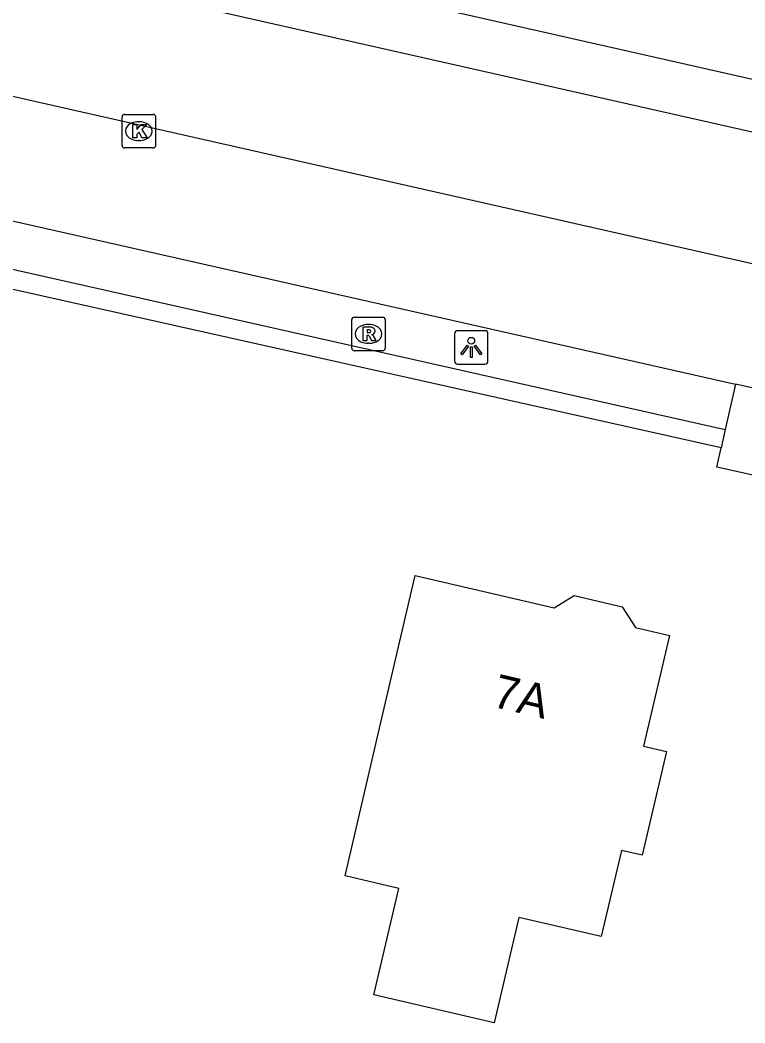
# Model space of a CAD drawing. Extents: x 161771 to 163125, y 382479 to 383177.
# Drawn here: x 162286.79 to 162308.4, y 383020.61 to 383050.51 of the extents above; entities that cross this region are included whole.
import ezdxf

# ---------------------------------------------------------------- set-up
doc = ezdxf.new("R2010")
doc.units = 0
for name, color, linetype in [('IMGEO_Berm_open', 7, 'Continuous'), ('IMGEO_Fietspad_gesloten', 7, 'Continuous'), ('IMGEO_Kolk', 7, 'Continuous'), ('IMGEO_Lichtpunt', 7, 'Continuous'), ('IMGEO_Pand', 7, 'Continuous'), ('IMGEO_Pand_nummerreeks', 7, 'Continuous'), ('IMGEO_Rijbaan_lokaal_gesloten', 7, 'Continuous'), ('IMGEO_Rioolput', 7, 'Continuous'), ('IMGEO_Voetpad_open', 7, 'Continuous')]:
    doc.layers.add(name, color=color, linetype=linetype)

msp = doc.modelspace()

# ---------------------------------------------------------------- linework, layer by layer
at = {"layer": 'IMGEO_Berm_open'}
for points in [[(162266.199, 383047.671), (162268.187, 383047.211), (162280.535, 383044.435), (162307.815, 383038.301)], [(162307.693, 383037.758), (162286.531, 383042.481), (162272.573, 383045.648)]]:
    msp.add_lwpolyline(points, dxfattribs=at)
at = {"layer": 'IMGEO_Fietspad_gesloten'}
msp.add_lwpolyline([(162315.791, 383045.55), (162268.595, 383056.213), (162263.052, 383057.484), (162259.124, 383058.343)], dxfattribs=at)
at = {"layer": 'IMGEO_Kolk'}
for p, q in [((162289.83, 383046.771), (162289.83, 383047.623)), ((162289.905, 383047.697), (162290.757, 383047.697)), ((162290.831, 383047.623), (162290.831, 383046.771)), ((162290.318, 383047.477), (162290.343, 383047.477)), ((162290.757, 383046.697), (162289.905, 383046.697)), ((162290.341, 383046.917), (162290.316, 383046.917))]:
    msp.add_line(p, q, dxfattribs=at)
for points in [[(162289.83, 383046.771), (162289.83, 383047.623)], [(162289.905, 383047.697), (162290.757, 383047.697)], [(162290.831, 383047.623), (162290.831, 383046.771)], [(162290.151, 383047.397), (162290.274, 383047.397), (162290.274, 383047.246), (162290.404, 383047.397), (162290.568, 383047.397), (162290.422, 383047.246), (162290.575, 383046.997), (162290.423, 383046.997), (162290.338, 383047.161), (162290.274, 383047.094), (162290.274, 383046.997), (162290.151, 383046.997), (162290.151, 383047.397)], [(162290.757, 383046.697), (162289.905, 383046.697)]]:
    msp.add_lwpolyline(points, dxfattribs=at)
for centre, start, end in [((162289.907, 383047.621), 91.552, 178.448), ((162289.907, 383047.621), 91.552, 178.448), ((162290.755, 383047.621), 1.552, 88.448), ((162290.755, 383047.621), 1.552, 88.448), ((162289.907, 383046.773), 181.552, 268.448), ((162289.907, 383046.773), 181.552, 268.448), ((162290.755, 383046.773), 271.552, 358.448), ((162290.755, 383046.773), 271.552, 358.448)]:
    msp.add_arc(centre, 0.0765, start, end, dxfattribs=at)
for centre, major_axis, ratio, start_param, end_param in [((162290.317, 383047.197), (-0.387, 0.002), 0.722429, 4.712389, 7.853982), ((162290.342, 383047.197), (-0.39, 0.002), 0.717154, 1.570796, 4.712389)]:
    msp.add_ellipse(centre, major_axis=major_axis, ratio=ratio, start_param=start_param, end_param=end_param, dxfattribs=at)
at = {"layer": 'IMGEO_Lichtpunt'}
for p, q in [((162299.743, 383041.151), (162299.743, 383040.344)), ((162299.743, 383041.151), (162299.743, 383040.344)), ((162300.645, 383041.246), (162299.837, 383041.246)), ((162300.645, 383041.246), (162299.837, 383041.246)), ((162300.739, 383040.344), (162300.739, 383041.151)), ((162300.739, 383040.344), (162300.739, 383041.151)), ((162299.837, 383040.25), (162300.645, 383040.25)), ((162299.837, 383040.25), (162300.645, 383040.25))]:
    msp.add_line(p, q, dxfattribs=at)
for points in [[(162300.117, 383040.815), (162300.156, 383040.787), (162299.968, 383040.525), (162299.93, 383040.552), (162300.117, 383040.815)], [(162300.219, 383040.767), (162300.266, 383040.767), (162300.266, 383040.445), (162300.219, 383040.445), (162300.219, 383040.767)], [(162300.329, 383040.787), (162300.367, 383040.814), (162300.554, 383040.552), (162300.515, 383040.524), (162300.329, 383040.787)]]:
    msp.add_lwpolyline(points, dxfattribs=at)
msp.add_circle((162300.242, 383040.949), 0.0994, dxfattribs=at)
for centre, start, end in [((162299.837, 383041.151), 90, 180), ((162299.837, 383041.151), 90, 180), ((162300.645, 383041.151), 0, 90), ((162300.645, 383041.151), 0, 90), ((162299.837, 383040.344), 180, 270), ((162299.837, 383040.344), 180, 270), ((162300.645, 383040.344), 270, 0), ((162300.645, 383040.344), 270, 360)]:
    msp.add_arc(centre, 0.0946, start, end, dxfattribs=at)
at = {"layer": 'IMGEO_Pand'}
msp.add_lwpolyline([(162304.719, 383025.754), (162304.118, 383023.183), (162301.664, 383023.756), (162300.929, 383020.608), (162297.34, 383021.447), (162298.081, 383024.617), (162296.48, 383024.991), (162297.578, 383029.691), (162298.573, 383033.948), (162302.711, 383032.981), (162303.309, 383033.352), (162304.743, 383033.017), (162305.135, 383032.399), (162306.148, 383032.163), (162305.376, 383028.86), (162306.065, 383028.7), (162305.342, 383025.608), (162304.719, 383025.754)], dxfattribs=at)
at = {"layer": 'IMGEO_Rijbaan_lokaal_gesloten'}
for points in [[(162270.405, 383051.883), (162283.923, 383048.832), (162329.67, 383038.487), (162387.404, 383025.398)], [(162269.608, 383048.319), (162269.978, 383048.272), (162271.762, 383047.863), (162308.119, 383039.657)], [(162312.021, 383038.776), (162311.795, 383038.827), (162311.766, 383038.834), (162308.119, 383039.657)]]:
    msp.add_lwpolyline(points, dxfattribs=at)
at = {"layer": 'IMGEO_Rioolput'}
for p, q in [((162296.676, 383040.724), (162296.676, 383041.576)), ((162296.751, 383041.65), (162297.603, 383041.65)), ((162297.677, 383041.576), (162297.677, 383040.724)), ((162297.164, 383041.43), (162297.189, 383041.43)), ((162297.187, 383040.87), (162297.162, 383040.87)), ((162297.603, 383040.65), (162296.751, 383040.65))]:
    msp.add_line(p, q, dxfattribs=at)
for points in [[(162296.676, 383040.724), (162296.676, 383041.576)], [(162296.751, 383041.65), (162297.603, 383041.65)], [(162297.677, 383041.576), (162297.677, 383040.724)], [(162297.265, 383041.348), (162297.013, 383041.35), (162297.013, 383040.95)], [(162297.013, 383040.95), (162297.137, 383040.95), (162297.137, 383041.112), (162297.148, 383041.112)], [(162297.191, 383041.269), (162297.137, 383041.269), (162297.137, 383041.188)], [(162297.137, 383041.188), (162297.189, 383041.188)], [(162297.195, 383041.083), (162297.266, 383040.95), (162297.406, 383040.95), (162297.341, 383041.076)], [(162297.603, 383040.65), (162296.751, 383040.65)]]:
    msp.add_lwpolyline(points, dxfattribs=at)
for centre, radius, start, end in [((162296.753, 383041.574), 0.0765, 91.552, 178.448), ((162296.753, 383041.574), 0.0765, 91.552, 178.448), ((162297.601, 383041.574), 0.0765, 1.552, 88.448), ((162297.601, 383041.574), 0.0765, 1.552, 88.448), ((162297.264, 383041.238), 0.109, 350.3612, 89.416), ((162297.147, 383041.059), 0.0533, 26.0293, 88.6989), ((162297.173, 383041.377), 0.19, 274.7715, 282.9687), ((162297.197, 383041.173), 0.0964, 77.0061, 93.1865), ((162297.211, 383041.23), 0.0378, 276.6634, 79.6772), ((162297.262, 383041.238), 0.112, 277.5842, 350.9817), ((162297.246, 383041.023), 0.108, 29.5134, 73.7905), ((162296.753, 383040.726), 0.0765, 181.552, 268.448), ((162296.753, 383040.726), 0.0765, 181.552, 268.448), ((162297.601, 383040.726), 0.0765, 271.552, 358.448), ((162297.601, 383040.726), 0.0765, 271.552, 358.448)]:
    msp.add_arc(centre, radius, start, end, dxfattribs=at)
for centre, major_axis, ratio, start_param, end_param in [((162297.163, 383041.15), (-0.387, 0.002), 0.722429, 4.712389, 7.853982), ((162297.188, 383041.15), (-0.39, 0.002), 0.717154, 1.570796, 4.712389)]:
    msp.add_ellipse(centre, major_axis=major_axis, ratio=ratio, start_param=start_param, end_param=end_param, dxfattribs=at)
at = {"layer": 'IMGEO_Voetpad_open'}
for points in [[(162250.097, 383061.898), (162272.461, 383056.925), (162316.154, 383047.05)], [(162308.119, 383039.657), (162307.815, 383038.301)], [(162307.815, 383038.301), (162307.693, 383037.758)], [(162315.135, 383035.503), (162307.564, 383037.18), (162307.693, 383037.758)]]:
    msp.add_lwpolyline(points, dxfattribs=at)

# ---------------------------------------------------------------- texts
at = {"layer": 'IMGEO_Pand_nummerreeks'}
msp.add_text('7A', height=1, rotation=346.7418, dxfattribs=at).set_placement((162300.824, 383030.047))

doc.saveas('drawing.dxf')
